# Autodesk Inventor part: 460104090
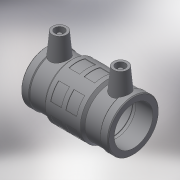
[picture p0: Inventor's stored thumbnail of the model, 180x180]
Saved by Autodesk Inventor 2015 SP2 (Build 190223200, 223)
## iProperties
Created: 2017-06
Part Number: 460104090
Material: Generic
Description: PLASSON LIGHTFIT COUPLER 90
Document SubType Name: Modeling
Designer: KIM
Mass: 89.5427 g
Surface Area: 304.58 cm^2
Volume: 89.5427 cm^3
Density: 1 g/cm^3
Appearance: Default
Author: KIM
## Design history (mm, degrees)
derived "460104.ipt"
feature "Solid1::460104.ipt"
tag "TaggingFeature1"
body "Solid1"
other parameters: "d13" = 148, "d14" = 17.6296, "d15" = 72, "d16" = 72, "d17" = 89.1, "d19" = 3.52592, "d20" = 168 deg, "d22" = 101.52, "d23" = 108, "d24" = 98.4744, "d25" = 135 deg, "d26" = 59.2, "d27" = 135 deg, "d29" = 69, "d35" = 15, "d39" = 5 deg, "d44" = 4, "d46" = 14, "d47" = 0, "d52" = 105.84, "d53" = 7.4, "d54" = 7.4, "d55" = 7.4, "d56" = 35 deg, "d58" = 360 deg, "d60" = 14.4, "d61" = 135 deg, "d62" = 62.16, "d63" = 3, "d64" = 0, "L_" = 148, "L_1" = 72, "D_" = 108, "A_" = 69, "d_2" = 12
